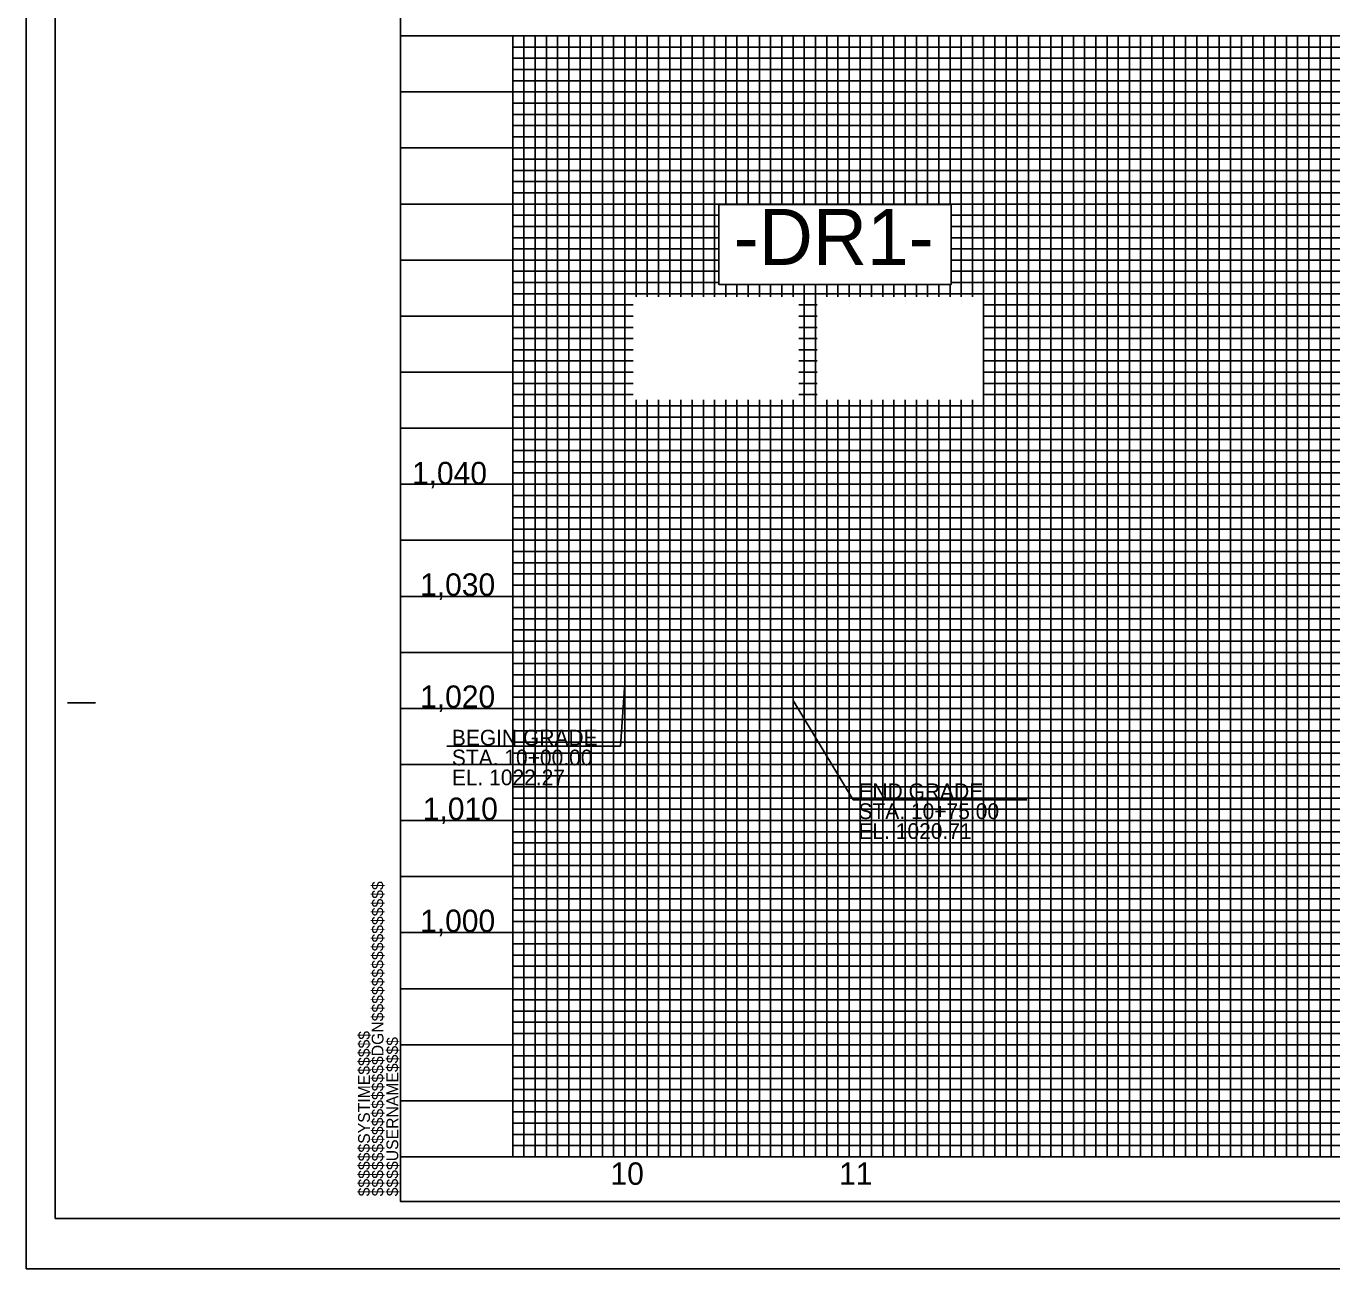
# Model space of a CAD drawing. Extents: x 1427348 to 1429459, y 856278 to 857378.
# Drawn here: x 1427597 to 1428179, y 856278 to 856832 of the extents above; entities that cross this region are included whole.
import ezdxf

# ---------------------------------------------------------------- set-up
doc = ezdxf.new("R2010")
doc.units = 0
for name, color, linetype in [('Exist Vertical Profile Horizontal Axis Label Major', 7, 'Continuous'), ('Exist Vertical Profile Vertical Axis Label', 7, 'Continuous'), ('Prop Grid Mask', 7, 'Continuous'), ('Prop Vertical Profile Curve Label', 7, 'Continuous'), ('Prop VPI Label', 7, 'Continuous'), ('Sheet Cutting Line CELL', 7, 'Continuous'), ('Sheet DOT Grid CELL', 7, 'Continuous'), ('Sheet Layout Profile Border Port 2', 7, 'Continuous'), ('Sheet Plot Border Inside CELL', 7, 'Continuous'), ('Sheet Plot Border Outside CELL', 7, 'Continuous'), ('Sheet Profile CELL', 7, 'Continuous'), ('Sheet Profile Grid Major CELL', 7, 'Continuous'), ('Sheet Profile Grid Middle CELL', 7, 'Continuous'), ('Sheet Profile Grid Minor CELL', 7, 'Continuous')]:
    doc.layers.add(name, color=color, linetype=linetype)

msp = doc.modelspace()

# ---------------------------------------------------------------- linework, layer by layer
at = {"layer": 'Prop Grid Mask'}
msp.add_lwpolyline([(1427905.83, 856752.4), (1428009.5, 856752.4), (1428009.5, 856716.76), (1427905.83, 856716.76)], close=True, dxfattribs=at)
at = {"layer": 'Prop VPI Label'}
for p, q in [((1427863.99, 856538.91), (1427862, 856510.73)), ((1427938.99, 856531.11), (1427965.85, 856486.78)), ((1427862, 856510.73), (1427784.54, 856510.73)), ((1428043.31, 856486.78), (1427965.85, 856486.78))]:
    msp.add_line(p, q, dxfattribs=at)
at = {"layer": 'Sheet Cutting Line CELL'}
for p, q in [((1427596.99, 857377.58), (1427596.99, 856277.58)), ((1427596.99, 856277.58), (1429280.99, 856277.58))]:
    msp.add_line(p, q, dxfattribs=at)
at = {"layer": 'Sheet DOT Grid CELL'}
for p, q in [((1427763.99, 856827.58), (1429263.88, 856827.58)), ((1427813.99, 856827.58), (1427813.99, 856327.58)), ((1427863.99, 856827.58), (1427863.99, 856327.58)), ((1427913.99, 856827.58), (1427913.99, 856752.4)), ((1427963.99, 856827.58), (1427963.99, 856752.4)), ((1428013.99, 856827.58), (1428013.99, 856711.23)), ((1428063.99, 856827.58), (1428063.99, 856327.58)), ((1428113.99, 856827.58), (1428113.99, 856327.58)), ((1428163.99, 856827.58), (1428163.99, 856327.58)), ((1427763.99, 856777.58), (1429263.88, 856777.58)), ((1427763.99, 856727.58), (1427905.83, 856727.58)), ((1428009.5, 856727.58), (1428350.45, 856727.58)), ((1427913.99, 856716.76), (1427913.99, 856711.23)), ((1427963.99, 856716.76), (1427963.99, 856711.23)), ((1427763.99, 856677.58), (1427867.72, 856677.58)), ((1427941.5, 856677.58), (1427949.81, 856677.58)), ((1428023.59, 856677.58), (1429263.88, 856677.58)), ((1427913.99, 856665.19), (1427913.99, 856327.58)), ((1427963.99, 856665.19), (1427963.99, 856327.58)), ((1428013.99, 856665.19), (1428013.99, 856327.58)), ((1427763.99, 856627.58), (1428411.65, 856627.58)), ((1427763.99, 856577.58), (1428330.81, 856577.58)), ((1427763.99, 856527.58), (1429263.88, 856527.58)), ((1427763.99, 856477.58), (1429263.88, 856477.58)), ((1427763.99, 856427.58), (1429263.88, 856427.58)), ((1427763.99, 856377.58), (1429263.88, 856377.58))]:
    msp.add_line(p, q, dxfattribs=at)
at = {"layer": 'Sheet Layout Profile Border Port 2'}
msp.add_lwpolyline([(1427813.99, 856827.58), (1429213.99, 856827.58), (1429213.99, 856327.58), (1427813.99, 856327.58)], close=True, dxfattribs=at)
at = {"layer": 'Sheet Plot Border Inside CELL'}
for p, q in [((1427609.99, 857355.13), (1427609.99, 856300.03)), ((1427609.99, 856300.03), (1429276.49, 856300.03))]:
    msp.add_line(p, q, dxfattribs=at)
at = {"layer": 'Sheet Plot Border Outside CELL'}
msp.add_lwpolyline([(1427596.99, 856277.58), (1429280.99, 856277.58), (1429280.99, 857377.58), (1427596.99, 857377.58)], close=True, dxfattribs=at)
at = {"layer": 'Sheet Profile CELL'}
for p, q in [((1427763.99, 856827.58), (1429263.99, 856827.58)), ((1427615.49, 856530.08), (1427627.99, 856530.08)), ((1429263.99, 856327.58), (1427763.99, 856327.58)), ((1427763.99, 856307.58), (1429263.99, 856307.58)), ((1427763.99, 856307.58), (1427763.99, 856307.58)), ((1427763.99, 856307.58), (1427763.99, 856307.58)), ((1427763.99, 856307.58), (1427763.99, 856307.58)), ((1427763.99, 856307.58), (1427763.99, 856307.58)), ((1427763.99, 856307.58), (1427763.99, 856307.58)), ((1427763.99, 856307.58), (1427763.99, 856307.58)), ((1427763.99, 856307.58), (1427763.99, 856307.58))]:
    msp.add_line(p, q, dxfattribs=at)
msp.add_lwpolyline([(1429263.99, 857347.58), (1427763.99, 857347.58), (1427763.99, 856307.58), (1429263.99, 856307.58)], close=True, dxfattribs=at)
msp.add_lwpolyline([(1427801.49, 856307.58), (1427801.49, 856307.58)], dxfattribs=at)
at = {"layer": 'Sheet Profile Grid Major CELL'}
msp.add_line((1427763.99, 856327.58), (1427763.99, 856327.58), dxfattribs=at)
for points in [[(1427813.99, 856827.58), (1427813.99, 856327.58), (1427863.99, 856327.58), (1427863.99, 856827.58), (1427913.99, 856827.58), (1427913.99, 856752.4)], [(1427963.99, 856752.4), (1427963.99, 856827.58), (1428013.99, 856827.58), (1428013.99, 856711.23)], [(1428013.99, 856665.19), (1428013.99, 856327.58), (1428063.99, 856327.58), (1428063.99, 856827.58), (1428113.99, 856827.58), (1428113.99, 856327.58), (1428163.99, 856327.58), (1428163.99, 856827.58), (1428213.99, 856827.58), (1428213.99, 856327.58), (1428263.99, 856327.58), (1428263.99, 856827.58), (1428313.99, 856827.58), (1428313.99, 856677.37)], [(1429263.99, 856777.58), (1427763.99, 856777.58)], [(1427905.83, 856727.58), (1427763.99, 856727.58), (1427763.99, 856677.58), (1427867.72, 856677.58)], [(1428350.45, 856727.58), (1428009.5, 856727.58)], [(1427913.99, 856716.76), (1427913.99, 856711.23)], [(1427963.99, 856711.23), (1427963.99, 856716.76)], [(1427941.5, 856677.58), (1427949.81, 856677.58)], [(1428023.59, 856677.58), (1429263.99, 856677.58)], [(1427913.99, 856665.19), (1427913.99, 856327.58), (1427963.99, 856327.58), (1427963.99, 856665.19)], [(1428411.65, 856627.58), (1427763.99, 856627.58), (1427763.99, 856577.58), (1428330.81, 856577.58)], [(1429263.99, 856527.58), (1427763.99, 856527.58), (1427763.99, 856477.58), (1429263.99, 856477.58)], [(1429263.99, 856427.58), (1427763.99, 856427.58), (1427763.99, 856427.58), (1427763.99, 856377.58), (1429263.99, 856377.58)], [(1429263.99, 856327.58), (1427763.99, 856327.58)]]:
    msp.add_lwpolyline(points, dxfattribs=at)
at = {"layer": 'Sheet Profile Grid Middle CELL'}
for points in [[(1427788.99, 856827.58), (1427838.99, 856827.58), (1427838.99, 856327.58), (1427888.99, 856327.58), (1427888.99, 856665.19)], [(1427888.99, 856711.23), (1427888.99, 856827.58), (1427938.99, 856827.58), (1427938.99, 856752.4)], [(1427988.99, 856752.4), (1427988.99, 856827.58), (1428038.99, 856827.58), (1428038.99, 856327.58), (1428088.99, 856327.58), (1428088.99, 856827.58), (1428138.99, 856827.58), (1428138.99, 856327.58), (1428188.99, 856327.58), (1428188.99, 856827.58), (1428238.99, 856827.58), (1428238.99, 856327.58), (1428288.99, 856327.58), (1428288.99, 856827.58), (1428338.99, 856827.58), (1428338.99, 856677.37)], [(1427763.99, 856802.58), (1429263.99, 856802.58)], [(1428350.45, 856752.58), (1427763.99, 856752.58), (1427763.99, 856702.58), (1427867.72, 856702.58)], [(1427938.99, 856716.76), (1427938.99, 856711.23)], [(1427988.99, 856711.23), (1427988.99, 856716.76)], [(1427941.5, 856702.58), (1427949.81, 856702.58)], [(1428023.59, 856702.58), (1429263.99, 856702.58)], [(1427938.99, 856665.19), (1427938.99, 856327.58), (1427988.99, 856327.58), (1427988.99, 856665.19)], [(1428290.23, 856652.58), (1427763.99, 856652.58), (1427763.99, 856602.58), (1428330.81, 856602.58)], [(1429263.99, 856552.58), (1427763.99, 856552.58), (1427763.99, 856502.58), (1429263.99, 856502.58)], [(1429263.99, 856452.58), (1427763.99, 856452.58), (1427763.99, 856402.58), (1429263.99, 856402.58)], [(1429263.99, 856352.58), (1427763.99, 856352.58)]]:
    msp.add_lwpolyline(points, dxfattribs=at)
at = {"layer": 'Sheet Profile Grid Minor CELL'}
for p, q in [((1427813.99, 856822.58), (1429213.99, 856822.58)), ((1429213.99, 856817.58), (1427813.99, 856817.58)), ((1427813.99, 856812.58), (1429213.99, 856812.58)), ((1429213.99, 856807.58), (1427813.99, 856807.58)), ((1427813.99, 856797.58), (1429213.99, 856797.58)), ((1429213.99, 856792.58), (1427813.99, 856792.58)), ((1427813.99, 856787.58), (1429213.99, 856787.58)), ((1429213.99, 856782.58), (1427813.99, 856782.58)), ((1427813.99, 856772.58), (1429213.99, 856772.58)), ((1429213.99, 856767.58), (1427813.99, 856767.58)), ((1427813.99, 856762.58), (1429213.99, 856762.58)), ((1428350.45, 856757.58), (1427813.99, 856757.58)), ((1427813.99, 856747.58), (1427905.83, 856747.58)), ((1427905.83, 856742.58), (1427813.99, 856742.58)), ((1428009.5, 856747.58), (1428350.45, 856747.58)), ((1428350.45, 856742.58), (1428009.5, 856742.58)), ((1427813.99, 856737.58), (1427905.83, 856737.58)), ((1428009.5, 856737.58), (1428350.45, 856737.58)), ((1427905.83, 856732.58), (1427813.99, 856732.58)), ((1428350.45, 856732.58), (1428009.5, 856732.58)), ((1427813.99, 856722.58), (1427905.83, 856722.58)), ((1428009.5, 856722.58), (1428350.45, 856722.58)), ((1427905.83, 856717.58), (1427813.99, 856717.58)), ((1429213.99, 856717.58), (1428009.5, 856717.58)), ((1427813.99, 856712.58), (1429213.99, 856712.58)), ((1427867.72, 856707.58), (1427813.99, 856707.58)), ((1427949.81, 856707.58), (1427941.5, 856707.58)), ((1429213.99, 856707.58), (1428023.59, 856707.58)), ((1427813.99, 856697.58), (1427867.72, 856697.58)), ((1427941.5, 856697.58), (1427949.81, 856697.58)), ((1428023.59, 856697.58), (1429213.99, 856697.58)), ((1427867.72, 856692.58), (1427813.99, 856692.58)), ((1427949.81, 856692.58), (1427941.5, 856692.58)), ((1429213.99, 856692.58), (1428023.59, 856692.58)), ((1427813.99, 856687.58), (1427867.72, 856687.58)), ((1427941.5, 856687.58), (1427949.81, 856687.58)), ((1428023.59, 856687.58), (1429213.99, 856687.58)), ((1427867.72, 856682.58), (1427813.99, 856682.58)), ((1427949.81, 856682.58), (1427941.5, 856682.58)), ((1429213.99, 856682.58), (1428023.59, 856682.58)), ((1427813.99, 856672.58), (1427867.72, 856672.58)), ((1427941.5, 856672.58), (1427949.81, 856672.58)), ((1428023.59, 856672.58), (1428290.23, 856672.58)), ((1427867.72, 856667.58), (1427813.99, 856667.58)), ((1427949.81, 856667.58), (1427941.5, 856667.58)), ((1428290.23, 856667.58), (1428023.59, 856667.58)), ((1427813.99, 856662.58), (1428290.23, 856662.58)), ((1428290.23, 856657.58), (1427813.99, 856657.58)), ((1427813.99, 856647.58), (1428290.23, 856647.58)), ((1428290.23, 856642.58), (1427813.99, 856642.58)), ((1427813.99, 856637.58), (1428290.23, 856637.58)), ((1428411.65, 856632.67), (1427813.99, 856632.73)), ((1427813.99, 856622.58), (1429213.99, 856622.58)), ((1429213.99, 856617.58), (1427813.99, 856617.58)), ((1427813.99, 856612.58), (1429213.99, 856612.58)), ((1428330.81, 856607.58), (1427813.99, 856607.58)), ((1427813.99, 856597.58), (1428330.81, 856597.58)), ((1428330.81, 856592.58), (1427813.99, 856592.58)), ((1427813.99, 856587.58), (1428330.81, 856587.58)), ((1428330.81, 856582.58), (1427813.99, 856582.58)), ((1427813.99, 856572.58), (1428330.81, 856572.58)), ((1428330.81, 856567.58), (1427813.99, 856567.58)), ((1427813.99, 856562.58), (1429213.99, 856562.58)), ((1429213.99, 856557.58), (1427813.99, 856557.58)), ((1427813.99, 856547.58), (1429213.99, 856547.58)), ((1429213.99, 856542.58), (1427813.99, 856542.58)), ((1427813.99, 856537.58), (1429213.99, 856537.58)), ((1429213.99, 856532.58), (1427813.99, 856532.58)), ((1427813.99, 856522.58), (1429213.99, 856522.58)), ((1429213.99, 856517.58), (1427813.99, 856517.58)), ((1427813.99, 856512.58), (1429213.99, 856512.58)), ((1429213.99, 856507.58), (1427813.99, 856507.58)), ((1427813.99, 856497.58), (1429213.99, 856497.58)), ((1429213.99, 856492.58), (1427813.99, 856492.58)), ((1427813.99, 856487.58), (1429213.99, 856487.58)), ((1429213.99, 856482.58), (1427813.99, 856482.58)), ((1427813.99, 856472.58), (1429213.99, 856472.58)), ((1429213.99, 856467.58), (1427813.99, 856467.58)), ((1427813.99, 856462.58), (1429213.99, 856462.58)), ((1429213.99, 856457.58), (1427813.99, 856457.58)), ((1427813.99, 856447.58), (1429213.99, 856447.58)), ((1429213.99, 856442.58), (1427813.99, 856442.58)), ((1427813.99, 856437.58), (1429213.99, 856437.58)), ((1429213.99, 856432.58), (1427813.99, 856432.58)), ((1427813.99, 856422.58), (1429213.99, 856422.58)), ((1429213.99, 856417.58), (1427813.99, 856417.58)), ((1427813.99, 856412.58), (1429213.99, 856412.58)), ((1429213.99, 856407.58), (1427813.99, 856407.58)), ((1427813.99, 856397.58), (1429213.99, 856397.58)), ((1429213.99, 856392.58), (1427813.99, 856392.58)), ((1427813.99, 856387.58), (1429213.99, 856387.58)), ((1429213.99, 856382.58), (1427813.99, 856382.58)), ((1427813.99, 856372.58), (1429213.99, 856372.58)), ((1429213.99, 856367.58), (1427813.99, 856367.58)), ((1427813.99, 856362.58), (1429213.99, 856362.58)), ((1429213.99, 856357.58), (1427813.99, 856357.58)), ((1427813.99, 856347.58), (1429213.99, 856347.58)), ((1429213.99, 856342.58), (1427813.99, 856342.58)), ((1427813.99, 856337.58), (1429213.99, 856337.58)), ((1427813.99, 856332.58), (1429213.99, 856332.58))]:
    msp.add_line(p, q, dxfattribs=at)
for points in [[(1427813.99, 856827.58), (1427818.99, 856827.58), (1427818.99, 856327.58), (1427823.99, 856327.58), (1427823.99, 856827.58), (1427828.99, 856827.58), (1427828.99, 856327.58), (1427833.99, 856327.58), (1427833.99, 856827.58), (1427843.99, 856827.58), (1427843.99, 856327.58), (1427848.99, 856327.58), (1427848.99, 856827.58), (1427853.99, 856827.58), (1427853.99, 856327.58), (1427858.99, 856327.58), (1427868.99, 856327.58), (1427873.99, 856327.58), (1427873.99, 856665.19)], [(1427858.99, 856327.58), (1427858.99, 856827.58), (1427868.99, 856827.58), (1427868.99, 856711.23)], [(1427873.99, 856711.23), (1427873.99, 856827.58), (1427878.99, 856827.58), (1427878.99, 856711.23)], [(1427883.99, 856711.23), (1427883.99, 856827.58), (1427893.99, 856827.58), (1427893.99, 856711.23)], [(1427898.99, 856711.23), (1427898.99, 856827.58), (1427903.99, 856827.58), (1427903.99, 856711.23)], [(1427908.99, 856752.4), (1427908.99, 856827.58), (1427918.99, 856827.58), (1427918.99, 856752.4)], [(1427923.99, 856752.4), (1427923.99, 856827.58), (1427928.99, 856827.58), (1427928.99, 856752.4)], [(1427933.99, 856752.4), (1427933.99, 856827.58), (1427943.99, 856827.58), (1427943.99, 856752.4)], [(1427948.99, 856752.4), (1427948.99, 856827.58), (1427953.99, 856827.58), (1427953.99, 856752.4)], [(1427958.99, 856752.4), (1427958.99, 856827.58), (1427968.99, 856827.58), (1427968.99, 856752.4)], [(1427973.99, 856752.4), (1427973.99, 856827.58), (1427978.99, 856827.58), (1427978.99, 856752.4)], [(1427983.99, 856752.4), (1427983.99, 856827.58), (1427993.99, 856827.58), (1427993.99, 856752.4)], [(1427998.99, 856752.4), (1427998.99, 856827.58), (1428003.99, 856827.58), (1428003.99, 856752.4)], [(1428008.99, 856752.4), (1428008.99, 856827.58), (1428018.99, 856827.58), (1428018.99, 856711.23)], [(1428018.99, 856665.19), (1428018.99, 856327.58), (1428023.99, 856327.58), (1428023.99, 856827.58), (1428028.99, 856827.58), (1428028.99, 856327.58)], [(1428028.99, 856327.58), (1428033.99, 856327.58), (1428033.99, 856827.58), (1428043.99, 856827.58), (1428043.99, 856327.58), (1428048.99, 856327.58), (1428048.99, 856827.58), (1428053.99, 856827.58), (1428053.99, 856327.58), (1428058.99, 856327.58), (1428058.99, 856827.58), (1428068.99, 856827.58), (1428068.99, 856327.58), (1428073.99, 856327.58), (1428073.99, 856827.58), (1428078.99, 856827.58), (1428078.99, 856327.58), (1428083.99, 856327.58), (1428083.99, 856827.58), (1428093.99, 856827.58), (1428093.99, 856327.58), (1428098.99, 856327.58), (1428098.99, 856827.58), (1428103.99, 856827.58), (1428103.99, 856327.58), (1428108.99, 856327.58), (1428108.99, 856827.58), (1428118.99, 856827.58), (1428118.99, 856327.58), (1428123.99, 856327.58), (1428123.99, 856827.58), (1428128.99, 856827.58), (1428128.99, 856327.58), (1428133.99, 856327.58), (1428133.99, 856827.58), (1428143.99, 856827.58), (1428143.99, 856327.58), (1428148.99, 856327.58), (1428148.99, 856827.58), (1428153.99, 856827.58), (1428153.99, 856327.58), (1428158.99, 856327.58), (1428158.99, 856827.58), (1428168.99, 856827.58), (1428168.99, 856327.58), (1428173.99, 856327.58), (1428173.99, 856827.58), (1428178.99, 856827.58), (1428178.99, 856327.58), (1428183.99, 856327.58)], [(1427908.99, 856711.23), (1427908.99, 856716.76)], [(1427918.99, 856716.76), (1427918.99, 856711.23)], [(1427923.99, 856711.23), (1427923.99, 856716.76)], [(1427928.99, 856716.76), (1427928.99, 856711.23)], [(1427933.99, 856711.23), (1427933.99, 856716.76)], [(1427943.99, 856716.76), (1427943.99, 856327.58), (1427948.99, 856327.58), (1427948.99, 856716.76)], [(1427953.99, 856716.76), (1427953.99, 856711.23)], [(1427958.99, 856711.23), (1427958.99, 856716.76)], [(1427968.99, 856716.76), (1427968.99, 856711.23)], [(1427973.99, 856711.23), (1427973.99, 856716.76)], [(1427978.99, 856716.76), (1427978.99, 856711.23)], [(1427983.99, 856711.23), (1427983.99, 856716.76)], [(1427993.99, 856716.76), (1427993.99, 856711.23)], [(1427998.99, 856711.23), (1427998.99, 856716.76)], [(1428003.99, 856716.76), (1428003.99, 856711.23)], [(1428008.99, 856711.23), (1428008.99, 856716.76)], [(1427868.99, 856665.19), (1427868.99, 856327.58)], [(1427878.99, 856665.19), (1427878.99, 856327.58), (1427883.99, 856327.58), (1427883.99, 856665.19)], [(1427893.99, 856665.19), (1427893.99, 856327.58), (1427898.99, 856327.58), (1427898.99, 856665.19)], [(1427903.99, 856665.19), (1427903.99, 856327.58), (1427908.99, 856327.58), (1427908.99, 856665.19)], [(1427918.99, 856665.19), (1427918.99, 856327.58), (1427923.99, 856327.58), (1427923.99, 856665.19)], [(1427928.99, 856665.19), (1427928.99, 856327.58), (1427933.99, 856327.58), (1427933.99, 856665.19)], [(1427953.99, 856665.19), (1427953.99, 856327.58), (1427958.99, 856327.58), (1427958.99, 856665.19)], [(1427968.99, 856665.19), (1427968.99, 856327.58), (1427973.99, 856327.58), (1427973.99, 856665.19)], [(1427978.99, 856665.19), (1427978.99, 856327.58), (1427983.99, 856327.58), (1427983.99, 856665.19)], [(1427993.99, 856665.19), (1427993.99, 856327.58), (1427998.99, 856327.58), (1427998.99, 856665.19)], [(1428003.99, 856665.19), (1428003.99, 856327.58), (1428008.99, 856327.58), (1428008.99, 856665.19)]]:
    msp.add_lwpolyline(points, dxfattribs=at)

# ---------------------------------------------------------------- texts
at = {"layer": 'Exist Vertical Profile Horizontal Axis Label Major'}
for s, p in [('10', (1427857.58, 856315.08)), ('11', (1427959.55, 856315.08))]:
    msp.add_text(s, height=10, dxfattribs=at).set_placement(p)
at = {"layer": 'Exist Vertical Profile Vertical Axis Label'}
for s, p in [('1,040', (1427769.05, 856627.58)), ('1,030', (1427772.69, 856577.83)), ('1,020', (1427772.69, 856527.83)), ('1,010', (1427773.89, 856477.83)), ('1,000', (1427772.69, 856427.83))]:
    msp.add_text(s, height=10, dxfattribs=at).set_placement(p)
at = {"layer": 'Prop Vertical Profile Curve Label'}
msp.add_text('-DR1-', height=25, dxfattribs=at).set_placement((1427912.54, 856725.42))
at = {"layer": 'Prop VPI Label'}
for s, p in [('BEGIN GRADE', (1427786.83, 856511.07)), ('STA. 10+00.00', (1427786.83, 856502.2)), ('EL. 1022.27', (1427786.83, 856493.32)), ('END GRADE', (1427968.15, 856487.12)), ('STA. 10+75.00', (1427968.15, 856478.25)), ('EL. 1020.71', (1427968.15, 856469.37))]:
    msp.add_text(s, height=7, dxfattribs=at).set_placement(p)
at = {"layer": 'Sheet Profile CELL'}
for s, p in [('$$$$$$$$$$$$$$$$DGN$$$$$$$$$$$$$$$$', (1427756.35, 856309.95)), ('$$$$$$SYSTIME$$$$$', (1427750.3, 856309.95)), ('$$$$USERNAME$$$$', (1427762.93, 856309.97))]:
    msp.add_text(s, height=5.25, rotation=90, dxfattribs=at).set_placement(p)

doc.saveas('drawing.dxf')
